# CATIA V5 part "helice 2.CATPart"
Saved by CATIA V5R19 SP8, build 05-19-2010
Part number: helice 2
Bounding box of the stored display mesh (mm): x -17.321 to 17.321, y -30 to 195, z -10 to 20
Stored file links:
  G:\EU_thinkMotion\CFAO_2010\MMS_groupe2\MMS_groupe2\A reprendre\splanchenault\Planchenault\helice 2.CATPart
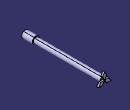
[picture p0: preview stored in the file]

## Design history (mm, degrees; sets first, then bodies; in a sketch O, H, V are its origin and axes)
Body1 (main body)
  Sketch1 on yz-plane, origin (0, 0, 0), H (0, 1, 0), V (0, 0, 1)
    line L1 (0, 7.5) -> (190, 7.5)
    point P1 (0, 7.5)
    line L2 (190, 7.5) -> (190, 0)
    point P3 (190, 0)
    line L3 (190, 0) -> (0, 0)
    line L4 (0, 0) -> (-30, 0)
    line L5 (-30, 0) -> (-30, 10)
    line L6 (0, 10) -> (-30, 10)
    line L7 (0, 10) -> (0, 7.5)
    length L3 = 190
    length L4 = 30
    length L5 = 10
    length L2 = 7.5
    coincidence: P1 V, P3 H
    horizontal: L1 H, L3 H, L4 H, L6 H
    vertical: L2 V, L5 V, L7 V
  Shaft1: profile Sketch1, axis Sketch1.L3, angle 360
  Sketch2 on face of Shaft1 from Sketch1.L2, origin (0, 190, 0), H (-1, 0, 0), V (0, 0, 1)
    construction line L1 (-12.2474, -7.0711) -> (12.2474, 7.0711)
    axis line L2 (12.2474, -7.0711) -> (-12.2474, 7.0711)
    line L3 (0, 0) -> (5.7735, 10)
    point P5 (5.7735, 10)
    line L4 (5.7735, 10) -> (0, 20)
    point P6 (0, 20)
    line L5 (0, 20) -> (-5.7735, 10)
    point P7 (-5.7735, 10)
    line L6 (-5.7735, 10) -> (0, 0)
    point P8 (-11.547, 0)
    point P9 (-17.3205, -10)
    line L7 (-17.3205, -10) -> (-11.547, 0)
    point P10 (0, 0)
    line L8 (-11.547, 0) -> (0, 0)
    point P11 (-5.7735, -10)
    line L9 (0, 0) -> (-5.7735, -10)
    line L10 (-5.7735, -10) -> (-17.3205, -10)
    point P12 (11.547, 0)
    point P13 (0, 0)
    line L11 (0, 0) -> (11.547, 0)
    point P14 (5.7735, -10)
    line L12 (5.7735, -10) -> (0, 0)
    point P15 (17.3205, -10)
    line L13 (17.3205, -10) -> (5.7735, -10)
    line L14 (11.547, 0) -> (17.3205, -10)
    angle L1 V = 120
    angle L2 V = 120
    coincidence: L1 O, L2 O, O P10, O P13, P10 P13
    perpendicularity: L3 L2, L4 L1
    parallelism: L5 L3, L6 L4
    symmetry: P7 P8 L2, P6 P9 L2, L5 L7 L2, O P10 L2, L6 L8 L2, P5 P11 L2, L3 L9 L2, L4 L10 L2, P5 P12 L1, O P13 L1, L3 L11 L1, P7 P14 L1, L6 L12 L1, P6 P15 L1, L5 L13 L1, L4 L14 L1
  Pad1: profile Sketch2, direction (0, 1, 0), length 5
